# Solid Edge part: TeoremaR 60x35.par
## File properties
Title: Terorema R 60x35
Author: DESYS
Template: Normal.par
Last saved by: i.fialdini
Revision: 34
Application: Solid Edge
Stile della faccia: Model Default
Coef. of Thermal Exp: 0.0
Thermal Conductivity: 0.0
Specific Heat: 0.0
Modulus of Elasticity: 0.0
Poisson's Ratio: 0.0
Yield Stress: 0.0
Ultimate Stress: 0.0
Elongation: 0.0
Tipo di contenuto documento: 0
Precisione: 0.990
Document Number: 5002
Revision: 0
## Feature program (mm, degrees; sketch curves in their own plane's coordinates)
sketch for "unnamed Protrusion 1" plane through (0, 0, 0) normal (0, 0, 1) x-axis (1, 0, 0)
  line (-170, -300) -> (170, -300)
  line (170, -300) -> (170, 300)
  line (170, 300) -> (-170, 300)
  line (-170, 300) -> (-170, -300)
  dimension (linear) = 170
  dimension (linear) = 170
extrude "unnamed Protrusion 1" add finite 140 along +normal
lofted cutout "unnamed LoftedCutout 1"
sketch for "ExtrudedCutout_6" plane through (-35, 0, 0) normal (1, 0, 0) x-axis (0, 1, 0)
  line (288, 0) -> (285.8118, 12)
  line (285.8118, 12) -> (-285.8118, 12)
  line (-288, 0) -> (-285.8118, 12)
  line (288, 0) -> (-288, 0)
extrude "ExtrudedCutout_6" cut finite 119 along -normal
sketch for "ExtrudedCutout_2" plane through (0, 0, 140) normal (0, 0, 1) x-axis (0, 1, 0)
  line (-235, -120) -> (235, -120)
  arc centre (235, -105) radius 15 from (235, -120) to (250, -105) ccw
  line (250, -105) -> (250, 150)
  line (-250, 150) -> (250, 150)
  line (-250, 150) -> (-250, -105)
  arc centre (-235, -105) radius 15 from (-250, -105) to (-235, -120) ccw
extrude "ExtrudedCutout_2" cut finite 45 along -normal  DraftAngle = 10 deg
sketch for "Scavo3" plane through (0, 0, 140) normal (0, 0, 1) x-axis (0, -1, 0)
  line (-250, -150) -> (250, -150)
  line (250, -150) -> (250, -50)
  line (250, -50) -> (-250, -50)
  line (-250, -50) -> (-250, -150)
extrude "Scavo3" cut finite 115 along -normal  Treatment1_DraftAngle = 10 deg
fillet "unnamed Round 1"
sketch for "ExtrudedProtrusion_2" plane through (0, 0, 95) normal (0, 0, 1) x-axis (0, -1, 0)
  circle centre (0, 30) radius 35
extrude "ExtrudedProtrusion_2" add finite 40 along +normal
sketch for "ExtrudedProtrusion_3" plane through (0, 0, 0) normal (0, -1, 0) x-axis (1, 0, 0)
  line (5.5887, 125) -> (-38.6813, 125)
  arc centre (-38.6813, 80) radius 45 from (-83.6331, 82.0825) to (-38.6813, 125) cw
  line (-83.6331, 82.0825) -> (-86.2776, 25)
  line (-86.2776, 25) -> (-70.2776, 25)
  line (-70.2776, 25) -> (-60.8489, 78.473)
  arc centre (-41.1527, 75) radius 20 from (-60.8489, 78.473) to (-41.1527, 95) cw
  line (-41.1527, 95) -> (5.5887, 95)
  line (5.5887, 95) -> (5.5887, 125)
  dimension (linear) = 86.2776
extrude "ExtrudedProtrusion_3" add finite 45 symmetric
sketch for "Foro_1" plane through (12.5, 0.0692, 135) normal (0, 0, 1) x-axis (0, -1, 0)
  hole centre (0.0692, 17.5) bore radius 25
hole "Foro_1" diameter 50 through
sketch for "Foro_2" plane through (-35, 0, 46) normal (1, 0, 0) x-axis (0, -1, 0)
  hole centre (0, 4) bore radius 10
hole "Foro_2" diameter 20 finite
fillet "Rotondo_7" radius 5
fillet "Rotondo_14" radius 5
fillet "Rotondo_17" radius 15
fillet "Rotondo_18" radius 6
fillet "Rotondo_19" radius 6
fillet "Rotondo_20" radius 6
sketch for "Foro_4" plane through (-155, 0, 12) normal (0, 0, -1) x-axis (0, -1, 0)
  hole centre (0, -50) bore radius 18
hole "Foro_4" diameter 36 through
fillet "Rotondo_21" radius 15
fillet "Rotondo_22" radius 5
sketch for "Foro_5" plane through (-170, 0, 50) normal (-1, 0, 0) x-axis (0, -1, 0)
  hole centre (-278, 68) bore radius 8
hole "Foro_5" finite
fillet "Rotondo_26" radius 6
sketch for "ExtrudedCutout_7" plane through (-170, 0, 72.5) normal (-1, 0, 0) x-axis (0, 1, 0)
extrude "ExtrudedCutout_7" cut finite 60 along -normal
sketch for "unnamed Cutout 1" #1 plane through (-170, 0, 72.5) normal (-1, 0, 0) x-axis (0, 1, 0)
  line (160, 7.5) -> (150, 7.5)
  arc centre (150, 17.5) radius 10 from (150, 7.5) to (150, 27.5) cw
  line (150, 27.5) -> (160, 27.5)
  arc centre (160, 17.5) radius 10 from (160, 7.5) to (160, 27.5) ccw
sketch for "unnamed Cutout 1" #2 plane through (-170, 0, 72.5) normal (-1, 0, 0) x-axis (0, 1, 0)
  line (-160, 7.5) -> (-150, 7.5)
  line (-150, 27.5) -> (-160, 27.5)
  dimension (linear) = 150
  dimension (linear) = 150
extrude "unnamed Cutout 1" cut through along -normal
fillet "Rotondo_31" radius 15
fillet "Rotondo_32" radius 5
fillet "Rotondo_33" radius 5
fillet "Rotondo_34" radius 5
fillet "Rotondo_35" radius 5
fillet "Rotondo_36" radius 5
fillet "Rotondo_37" radius 5
fillet "Rotondo_38" radius 5
fillet "Rotondo_39" radius 2
fillet "Rotondo_40" radius 5
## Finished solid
Body 1: solid body, 177 faces, 392 edges, 216 vertices.
  Faces by surface: cylinder 82, plane 34, blend 25, torus 24, sphere 10, cone 2
  Edges by curve: circle 166, line 165, ellipse 56, intersection 5
Bounding box of the edges (mm; curved faces can reach further): 340.000 x 600.000 x 140.000, from (-170, -300, 0) to (170, 300, 140).
Cylindrical faces by radius (mm): R5 x48, R6 x14, R8 x1, R10 x5, R15 x6, R18 x1, R20 x2, R25 x1, R35 x1, R45 x1, R75 x2
Conical faces (half-angle, radius in mm at the cone's reference point): 10 deg R15 x2
Toroidal faces (ring radius, tube radius in mm): R1 r5 x8, R2.8698 r5 x2, R12 r2 x1, R19.1955 r5 x2, R23 r5 x1, R25 r5 x2, R30 r5 x1, R40 r5 x4, R40 r15 x1, R80 r5 x2
Spherical faces by radius (mm): R5 x10
Planar faces by outward normal: +x 3, +y 2, +z 8, -x 2, -y 2, -z 5, oblique 12
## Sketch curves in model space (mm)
line (138, -272.5, 85) -> (-35, -272.5, 85)
line (-35, -272.5, 85) -> (-35, 272.5, 85)
line (-35, 272.5, 85) -> (138, 272.5, 85)
line (138, 272.5, 85) -> (138, -272.5, 85)
line (158, -288, 0) -> (-35, -288, 0)
line (-35, -288, 0) -> (-35, 288, 0)
line (-35, 288, 0) -> (158, 288, 0)
line (158, 288, 0) -> (158, -288, 0)
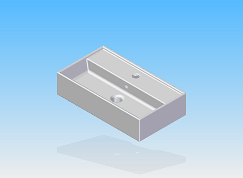
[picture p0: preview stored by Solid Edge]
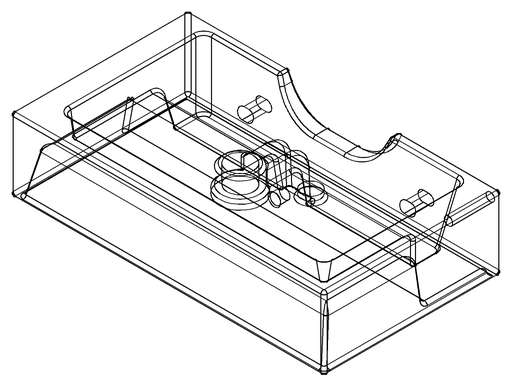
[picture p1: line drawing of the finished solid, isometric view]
